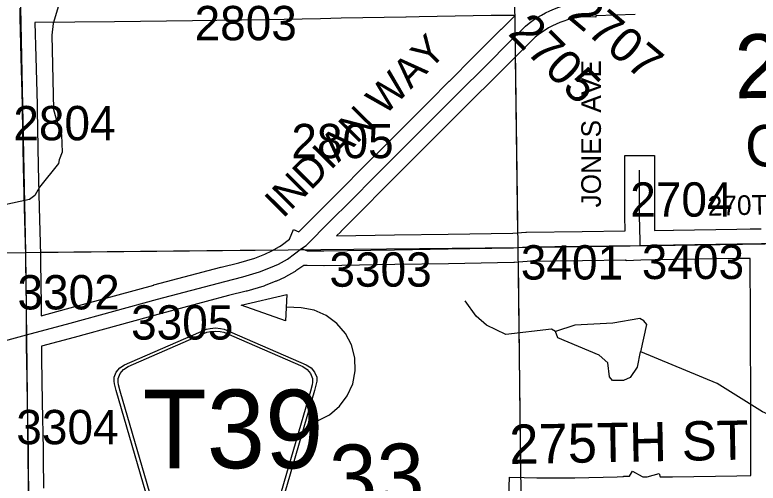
# Model space of a CAD drawing. Extents: x 23.6 to 68.7, y -63 to -29.
# Drawn here: x 40.707 to 42.22, y -51.095 to -50.14 of the extents above; entities that cross this region are included whole.
import ezdxf

# ---------------------------------------------------------------- set-up
doc = ezdxf.new("R2010")
doc.units = 0
for name, color, linetype in [('tdCoDirctArrow', 7, 'Continuous'), ('tdCoHydroRiver', 7, 'Continuous'), ('tdCoSecRdNmbr', 7, 'Continuous'), ('tdCoSecRdTxt', 7, 'Continuous'), ('tdCoSecRteBand', 7, 'Continuous'), ('tdCoSecRteCL', 7, 'Continuous'), ('tdCoSectLine', 7, 'Continuous'), ('tdCoSectLinePart', 7, 'Continuous'), ('tdCoSectNmbr', 7, 'Continuous'), ('tdCoShieldCoRteHrd', 7, 'Continuous'), ('tdCoStrucSecCoName', 7, 'Continuous'), ('tdCoSurfAsphalt', 7, 'Continuous'), ('tdCoSurfGravel', 7, 'Continuous')]:
    doc.layers.add(name, color=color, linetype=linetype)

msp = doc.modelspace()

# ---------------------------------------------------------------- linework, layer by layer
at = {"layer": 'tdCoDirctArrow'}
msp.add_lwpolyline([(41.2583, -50.7638), (41.1675, -50.7317), (41.2607, -50.71)], close=True, dxfattribs=at)
msp.add_lwpolyline([(41.3235, -50.9672), (41.3473, -50.955), (41.3678, -50.9377), (41.3839, -50.9163), (41.3948, -50.8919), (41.4, -50.8656), (41.3992, -50.8388), (41.3923, -50.8129), (41.3799, -50.7892), (41.3625, -50.7689), (41.3409, -50.7529), (41.3164, -50.7422), (41.2901, -50.7373), (41.2599, -50.7357)], dxfattribs=at)
at = {"layer": 'tdCoHydroRiver'}
for points in [[(40.8297, -50.0184), (40.8127, -50.0643), (40.7852, -50.1577), (40.7823, -50.1814), (40.7853, -50.3329), (40.7902, -50.3502), (40.8016, -50.3848), (40.8035, -50.4196), (40.7973, -50.4354), (40.7958, -50.4433), (40.7568, -50.491), (40.7475, -50.5085), (40.7365, -50.5165), (40.6829, -50.528), (40.6704, -50.5329), (40.6047, -50.603), (40.5798, -50.6395), (40.5691, -50.6744), (40.5503, -50.6872), (40.5298, -50.6889), (40.5188, -50.6938), (40.4846, -50.7478), (40.4564, -50.7733), (40.4296, -50.7814)], [(41.8077, -50.7857), (41.7998, -50.781), (41.7068, -50.7914), (41.6671, -50.7728), (41.6464, -50.7541), (41.624, -50.7227)], [(41.9818, -50.8267), (41.9939, -50.7713), (41.9875, -50.7635), (41.9795, -50.7588), (41.9244, -50.7688), (41.8471, -50.7727), (41.8077, -50.7857)], [(41.9239, -50.8856), (41.9175, -50.8778), (41.9141, -50.8494), (41.8966, -50.8338), (41.8126, -50.7983), (41.8077, -50.7857)], [(41.9818, -50.8267), (41.9802, -50.8267), (41.9742, -50.8583), (41.9602, -50.879), (41.946, -50.8854), (41.9239, -50.8856)], [(42.6171, -50.9059), (42.5901, -50.8903), (42.5602, -50.8985), (42.5382, -50.9082), (42.497, -50.8912), (42.4433, -50.8917), (42.3914, -50.9143), (42.346, -50.9495), (42.3083, -50.9704), (42.2815, -50.9722), (42.2292, -50.949), (42.1371, -50.8915), (41.9818, -50.8267)]]:
    msp.add_lwpolyline(points, dxfattribs=at)
at = {"layer": 'tdCoSecRteBand'}
for points in [[(40.7606, -50.7533), (40.812, -50.7395), (40.9897, -50.6907), (40.9898, -50.6906), (40.9899, -50.6906), (41.1266, -50.6544), (41.1268, -50.6543), (41.127, -50.6542), (41.1631, -50.6453), (41.1954, -50.6357), (41.2158, -50.6276), (41.23, -50.6213), (41.2455, -50.6125), (41.2489, -50.61), (41.2661, -50.5974), (41.274, -50.5776), (41.2853, -50.5821), (41.3281, -50.5396), (41.3689, -50.4985), (41.4197, -50.4472), (41.4198, -50.4471), (41.4198, -50.4471), (41.4642, -50.4027), (41.551, -50.3159), (41.5916, -50.275), (41.5917, -50.275), (41.5918, -50.2749), (41.6418, -50.2251), (41.6975, -50.1692), (41.6976, -50.1691), (41.6978, -50.1689), (41.7259, -50.1415), (41.7261, -50.1414), (41.7184, -50.1414), (41.677, -50.1413), (41.5301, -50.1438), (41.5038, -50.1446), (41.5036, -50.1446), (41.5034, -50.1446), (41.3715, -50.1469), (41.3296, -50.1479), (41.3296, -50.1479), (41.3295, -50.1479), (41.2179, -50.15), (41.2178, -50.15), (41.2177, -50.15), (41.0687, -50.152), (41.0687, -50.152), (41.0687, -50.152), (40.9096, -50.154), (40.9096, -50.154), (40.9096, -50.154), (40.7481, -50.1559), (40.7479, -50.1559), (40.7499, -50.2265), (40.7499, -50.2265), (40.7499, -50.2266), (40.7522, -50.3228), (40.7526, -50.3332), (40.7526, -50.3335), (40.7526, -50.3338), (40.7542, -50.4483), (40.7565, -50.5324), (40.7593, -50.6292), (40.7593, -50.6299), (40.7593, -50.6305), (40.7592, -50.6445), (40.7608, -50.7311), (40.7608, -50.7316), (40.7608, -50.732), (40.7606, -50.7533)], [(41.9702, -50.1392), (41.8898, -50.1422), (41.8898, -50.1447), (41.8628, -50.1438), (41.847, -50.1465), (41.8326, -50.1502), (41.8248, -50.1527), (41.8168, -50.1557), (41.809, -50.159), (41.8014, -50.1627), (41.7939, -50.1667), (41.7867, -50.171), (41.7796, -50.1757), (41.7727, -50.1807), (41.7667, -50.1855), (41.7398, -50.2117), (41.6842, -50.2675), (41.6842, -50.2676), (41.6841, -50.2676), (41.6341, -50.3174), (41.5935, -50.3583), (41.5935, -50.3583), (41.5934, -50.3583), (41.5066, -50.4451), (41.4623, -50.4895), (41.4116, -50.5407), (41.4115, -50.5407), (41.4115, -50.5408), (41.3706, -50.5819), (41.3705, -50.582), (41.3705, -50.5821), (41.3617, -50.5908), (41.4797, -50.5887), (41.4798, -50.5887), (41.4799, -50.5887), (41.5891, -50.5873), (41.7211, -50.5847), (41.7472, -50.583), (41.748, -50.5829), (41.7488, -50.5829), (41.862, -50.5813), (41.8621, -50.5813), (41.8621, -50.5813), (41.9496, -50.5803), (41.9492, -50.5501), (41.9492, -50.5499), (41.9492, -50.5498), (41.9491, -50.4564), (41.9491, -50.4264), (42.0091, -50.4264), (42.0091, -50.4564), (42.0092, -50.5495), (42.0096, -50.5796), (42.0475, -50.5786), (42.0477, -50.5786), (42.0478, -50.5786), (42.1772, -50.5768), (42.204, -50.5764), (42.204, -50.5763), (42.2043, -50.5763), (42.2043, -50.576), (42.2269, -50.576)], [(41.7124, -51.1422), (41.7143, -51.0823), (41.7443, -51.0832), (41.7697, -51.084), (41.8474, -51.0837), (41.9334, -51.0816), (41.9335, -51.0816), (41.9336, -51.0816), (41.9466, -51.0813), (41.9466, -51.0802), (41.9588, -51.0806), (41.9649, -51.0701), (41.9842, -51.0813), (41.986, -51.0814), (41.9864, -51.0814), (41.9943, -51.0816), (42.0186, -51.0746), (42.0207, -51.0817), (42.046, -51.0817), (42.1773, -51.0798), (42.2055, -51.0792), (42.2057, -51.0648), (42.2055, -50.9998), (42.2055, -50.9998), (42.2055, -50.9998), (42.2055, -50.9863), (42.2055, -50.9862), (42.2055, -50.9862), (42.2059, -50.9), (42.2052, -50.8119), (42.2052, -50.8119), (42.2052, -50.8119), (42.2047, -50.7425), (42.2041, -50.6516), (42.2041, -50.6514), (42.2041, -50.6511), (42.2042, -50.6364), (42.1782, -50.6368), (42.1781, -50.6368), (42.1781, -50.6368), (42.0488, -50.6386), (42.0107, -50.6396), (42.0107, -50.6397), (41.9813, -50.64), (41.952, -50.6416), (41.952, -50.6403), (41.9507, -50.6403), (41.8628, -50.6413), (41.7504, -50.6429), (41.7244, -50.6446), (41.7237, -50.6447), (41.723, -50.6447), (41.5902, -50.6473), (41.59, -50.6473), (41.5899, -50.6473), (41.4807, -50.6487), (41.3368, -50.6513), (41.3364, -50.6513), (41.3361, -50.6513), (41.302, -50.6511), (41.2964, -50.6511), (41.2951, -50.6506), (41.2794, -50.662), (41.278, -50.663), (41.2766, -50.6638), (41.2583, -50.6742), (41.2571, -50.6749), (41.2557, -50.6755), (41.2397, -50.6826), (41.2392, -50.6829), (41.2386, -50.6831), (41.2164, -50.692), (41.2151, -50.6925), (41.2138, -50.6929), (41.1795, -50.703), (41.1789, -50.7032), (41.1782, -50.7033), (41.1417, -50.7124), (41.0055, -50.7486), (40.8278, -50.7974), (40.8277, -50.7974), (40.8276, -50.7974), (40.7613, -50.8152), (40.7615, -50.8216), (40.7609, -50.8216), (40.7613, -50.8412), (40.7613, -50.8413), (40.7613, -50.8414), (40.7626, -50.9295), (40.7646, -51.0262), (40.7646, -51.0264), (40.7646, -51.0266), (40.7649, -51.0697), (40.7651, -51.0795), (40.7655, -51.1045)]]:
    msp.add_lwpolyline(points, dxfattribs=at)
at = {"layer": 'tdCoSecRteCL'}
for points in [[(40.7307, -50.7924), (40.7303, -50.7764), (40.7308, -50.7317), (40.7292, -50.6446), (40.7293, -50.6301), (40.7265, -50.5333), (40.7242, -50.4489), (40.7226, -50.3342), (40.7223, -50.3237), (40.72, -50.2273), (40.7177, -50.1459), (40.7178, -50.1262)], [(41.2908, -50.6166), (41.3, -50.6099), (41.3493, -50.5608), (41.3902, -50.5196), (41.441, -50.4683), (41.4854, -50.4239), (41.5722, -50.3371), (41.6129, -50.2962), (41.663, -50.2464), (41.7187, -50.1904), (41.7468, -50.163), (41.7545, -50.1569), (41.7625, -50.1511), (41.7707, -50.1456), (41.7791, -50.1406), (41.7878, -50.1359), (41.7966, -50.1317), (41.8057, -50.1278), (41.8149, -50.1244), (41.8243, -50.1213), (41.8408, -50.1171), (41.8608, -50.1137)], [(41.9804, -50.61), (41.9799, -50.6009), (41.9792, -50.5497), (41.9791, -50.4564)], [(41.2908, -50.6166), (41.3022, -50.6211), (41.3362, -50.6213), (41.4802, -50.6187), (41.5896, -50.6173), (41.7224, -50.6147), (41.7492, -50.6129), (41.8625, -50.6113), (41.9804, -50.61)], [(41.9804, -50.61), (42.0012, -50.6098), (42.0482, -50.6086), (42.1777, -50.6068), (42.2271, -50.606), (42.2343, -50.606)], [(40.7307, -50.7924), (40.8198, -50.7684), (40.9976, -50.7196), (41.1343, -50.6834), (41.171, -50.6742), (41.2053, -50.6641), (41.2275, -50.6552), (41.2435, -50.6481), (41.2618, -50.6377), (41.2908, -50.6166)], [(40.5804, -50.8328), (40.7307, -50.7924)], [(40.7355, -51.11), (40.7349, -51.07), (40.7346, -51.0268), (40.7326, -50.93), (40.7313, -50.8419), (40.7308, -50.8195), (40.7307, -50.7924)]]:
    msp.add_lwpolyline(points, dxfattribs=at)
at = {"layer": 'tdCoSectLine'}
for points in [[(41.7173, -49.6109), (41.7311, -50.6141)], [(40.7079, -49.6245), (40.7288, -50.6241)], [(41.7311, -50.6141), (42.7376, -50.599)], [(39.7253, -50.6386), (40.7288, -50.6241)], [(40.7288, -50.6241), (41.7311, -50.6141)], [(40.7288, -50.6241), (40.7345, -51.1539), (40.7489, -51.6298)], [(41.7311, -50.6141), (41.7431, -51.6156)]]:
    msp.add_lwpolyline(points, dxfattribs=at)
at = {"layer": 'tdCoSectLinePart'}
for points in [[(41.7246, -50.1414), (41.7246, -50.1425)], [(41.7258, -50.2254), (41.7307, -50.5841)], [(40.7588, -50.6238), (41.2335, -50.6191)], [(41.7315, -50.6441), (41.7367, -51.083)]]:
    msp.add_lwpolyline(points, dxfattribs=at)
at = {"layer": 'tdCoShieldCoRteHrd'}
for points in [[(40.9954, -51.1884), (40.9135, -50.9055), (40.9096, -50.8923), (40.9089, -50.8864), (40.9089, -50.8786), (40.9131, -50.8683), (40.9204, -50.8598), (40.93, -50.8532), (41.0972, -50.7808), (41.1047, -50.7792), (41.1152, -50.7783), (41.1256, -50.7792), (41.1331, -50.7808), (41.3004, -50.8532), (41.31, -50.8598), (41.3172, -50.8683), (41.3215, -50.8786), (41.3215, -50.8864), (41.3208, -50.8923), (41.3169, -50.9055), (41.2349, -51.1884)], [(41.0013, -51.182), (40.9215, -50.9068), (40.9178, -50.8941), (40.9171, -50.8885), (40.9171, -50.881), (40.9212, -50.8711), (40.9282, -50.8629), (40.9374, -50.8565), (41.0979, -50.7871), (41.1052, -50.7855), (41.1152, -50.7846), (41.1252, -50.7855), (41.1324, -50.7871), (41.293, -50.8565), (41.3022, -50.8629), (41.3092, -50.8711), (41.3132, -50.881), (41.3132, -50.8885), (41.3125, -50.8941), (41.3088, -50.9068), (41.2291, -51.182)]]:
    msp.add_lwpolyline(points, close=True, dxfattribs=at)
at = {"layer": 'tdCoSurfAsphalt'}
msp.add_lwpolyline([(40.5804, -50.8328), (40.7307, -50.7924), (40.8198, -50.7684), (40.9976, -50.7196), (41.1343, -50.6834), (41.171, -50.6742), (41.2053, -50.6641), (41.2275, -50.6552), (41.2435, -50.6481), (41.2618, -50.6377), (41.2908, -50.6166), (41.3, -50.6099), (41.3493, -50.5608), (41.3902, -50.5196), (41.441, -50.4683), (41.4854, -50.4239), (41.5722, -50.3371), (41.6129, -50.2962), (41.663, -50.2464), (41.7187, -50.1904), (41.7468, -50.163), (41.7545, -50.1569), (41.7625, -50.1511), (41.7707, -50.1456), (41.7791, -50.1406), (41.7878, -50.1359)], dxfattribs=at)
at = {"layer": 'tdCoSurfGravel'}
for points in [[(40.7355, -51.11), (40.7349, -51.07), (40.7346, -51.0268), (40.7326, -50.93), (40.7313, -50.8419), (40.7308, -50.8195), (40.7307, -50.7924), (40.7303, -50.7764), (40.7308, -50.7317), (40.7292, -50.6446), (40.7293, -50.6301), (40.7265, -50.5333), (40.7242, -50.4489), (40.7226, -50.3342), (40.7223, -50.3237), (40.72, -50.2273), (40.7177, -50.1459), (40.7178, -50.1262)], [(41.9804, -50.61), (41.9799, -50.6009), (41.9792, -50.5497), (41.9791, -50.4564)], [(41.2908, -50.6166), (41.3022, -50.6211), (41.3362, -50.6213), (41.4802, -50.6187), (41.5896, -50.6173), (41.7224, -50.6147), (41.7492, -50.6129), (41.8625, -50.6113), (41.9804, -50.61), (42.0012, -50.6098), (42.0482, -50.6086), (42.1777, -50.6068), (42.2271, -50.606), (42.2343, -50.606), (42.2541, -50.606), (42.3125, -50.605), (42.3815, -50.604), (42.5125, -50.602), (42.6574, -50.6002), (42.709, -50.5996)]]:
    msp.add_lwpolyline(points, dxfattribs=at)

# ---------------------------------------------------------------- texts
at = {"layer": 'tdCoSecRdNmbr'}
for s, rotation, p in [('2707', 320.0327, (41.829, -50.1444)), ('2803', 0.0322, (41.0729, -50.1919)), ('2705', 315.0319, (41.709, -50.1796)), ('2804', 0.0319, (40.7038, -50.3958)), ('2805', 0.0323, (41.27, -50.4323)), ('2704', 0.0328, (41.9601, -50.5515)), ('3401', 0.0327, (41.7373, -50.6796)), ('3403', 0.0329, (41.9837, -50.6786)), ('3303', 0.0324, (41.3475, -50.6942)), ('3302', 0.0319, (40.7123, -50.7405)), ('3305', 0.0321, (40.9436, -50.802)), ('3304', 0.0319, (40.7099, -51.0153))]:
    msp.add_text(s, height=0.07, rotation=rotation, dxfattribs=at).set_placement(p)
at = {"layer": 'tdCoSecRdTxt'}
for s, height, rotation, p in [('INDIAN WAY', 0.06, 45.3569, (41.2529, -50.5564)), ('JONES AVE', 0.04, 90, (41.9003, -50.5326)), ('270TH ST', 0.04, 1.315, (42.1183, -50.5496)), ('275TH ST', 0.08, 1.0685, (41.7145, -51.0555))]:
    msp.add_text(s, height=height, rotation=rotation, dxfattribs=at).set_placement(p)
at = {"layer": 'tdCoSectNmbr'}
for s, rotation, p in [('27', 1.0329, (42.1735, -50.3103)), ('33', 1.0323, (41.3484, -51.1467))]:
    msp.add_text(s, height=0.13, rotation=rotation, dxfattribs=at).set_placement(p)
at = {"layer": 'tdCoShieldCoRteHrd'}
msp.add_text('T39', height=0.16, dxfattribs=at).set_placement((40.9668, -51.0641))
at = {"layer": 'tdCoStrucSecCoName'}
msp.add_text('GF342666.0', height=0.085, dxfattribs=at).set_placement((42.194, -50.4491))

doc.saveas('drawing.dxf')
